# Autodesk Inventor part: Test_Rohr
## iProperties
Created: 2006-08
Material: Standard
Document SubType Name: Modeling
Part Number: Test_Rohr
Title: Al-Rohr
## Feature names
1. Extrusion1
2. Drehung1 [Revolution]
